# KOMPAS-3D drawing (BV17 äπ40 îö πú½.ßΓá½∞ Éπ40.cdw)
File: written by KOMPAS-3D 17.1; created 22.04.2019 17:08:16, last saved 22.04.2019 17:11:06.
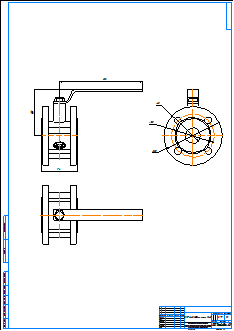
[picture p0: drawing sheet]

Sheet 1: A1, portrait

Title block, sheet 1: name: BV17 Ду40 МФ угл.сталь Ру40; material: Внимание! Данный продукт является объектом авторского права ООО «Торговый Дом АДЛ». / Запрещается изменение, копирование, распространение / (в том числе путем копирования на другие сайты и ресурсы в Интернете) / или любое иное использование информации и объектов без предварительного / согласия правообладателя (ООО «Торговый Дом АДЛ»).; mass: 5,79; sheets: 1; organisation: ООО "Торговый дом АДЛ"; sheet format: A1; stored path: \\adlc.lan\data\АДЛ_ПКД\3D-модели\ADL production\Краны шаровые серии BV\BV17 МФ угл.сталь Ру40\KOMPAS 2D\BV17 Ду40 МФ угл.сталь Ру40.cdw

Views: Вид 1, Проекционный вид 2, Проекционный вид 3
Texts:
  user
Dimensions and other numbers on the sheet: 212; 118; 94; 40; 110; 150; 1:1; 1; 5,79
